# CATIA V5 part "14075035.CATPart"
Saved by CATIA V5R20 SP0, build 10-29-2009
Part number: 14075035
Definition: NONE
Nomenclature: 14075035
Source: Unknown
Description: 14075035
Bounding box of the stored display mesh (mm): x -17.5 to 70, y -51.5 to 41.58, z -41.6 to 41.6
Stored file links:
  C:\Users\Utente\Desktop\IO LAVORO\3D X SITO CF\X SITO\PLASTICA\RF2\14075035.CATPart
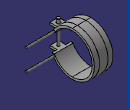
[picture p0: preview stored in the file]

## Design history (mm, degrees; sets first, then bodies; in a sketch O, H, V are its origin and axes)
Body1 "14075035" (main body)
  Solid1: solid without history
